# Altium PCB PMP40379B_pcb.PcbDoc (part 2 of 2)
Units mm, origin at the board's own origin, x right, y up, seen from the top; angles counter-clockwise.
Board outline 160 x 130 mm, 2 copper layers (Top Layer, Bottom Layer), stack 1.575 mm thick; 126 components, 53 nets, 295 pads, 84 vias.
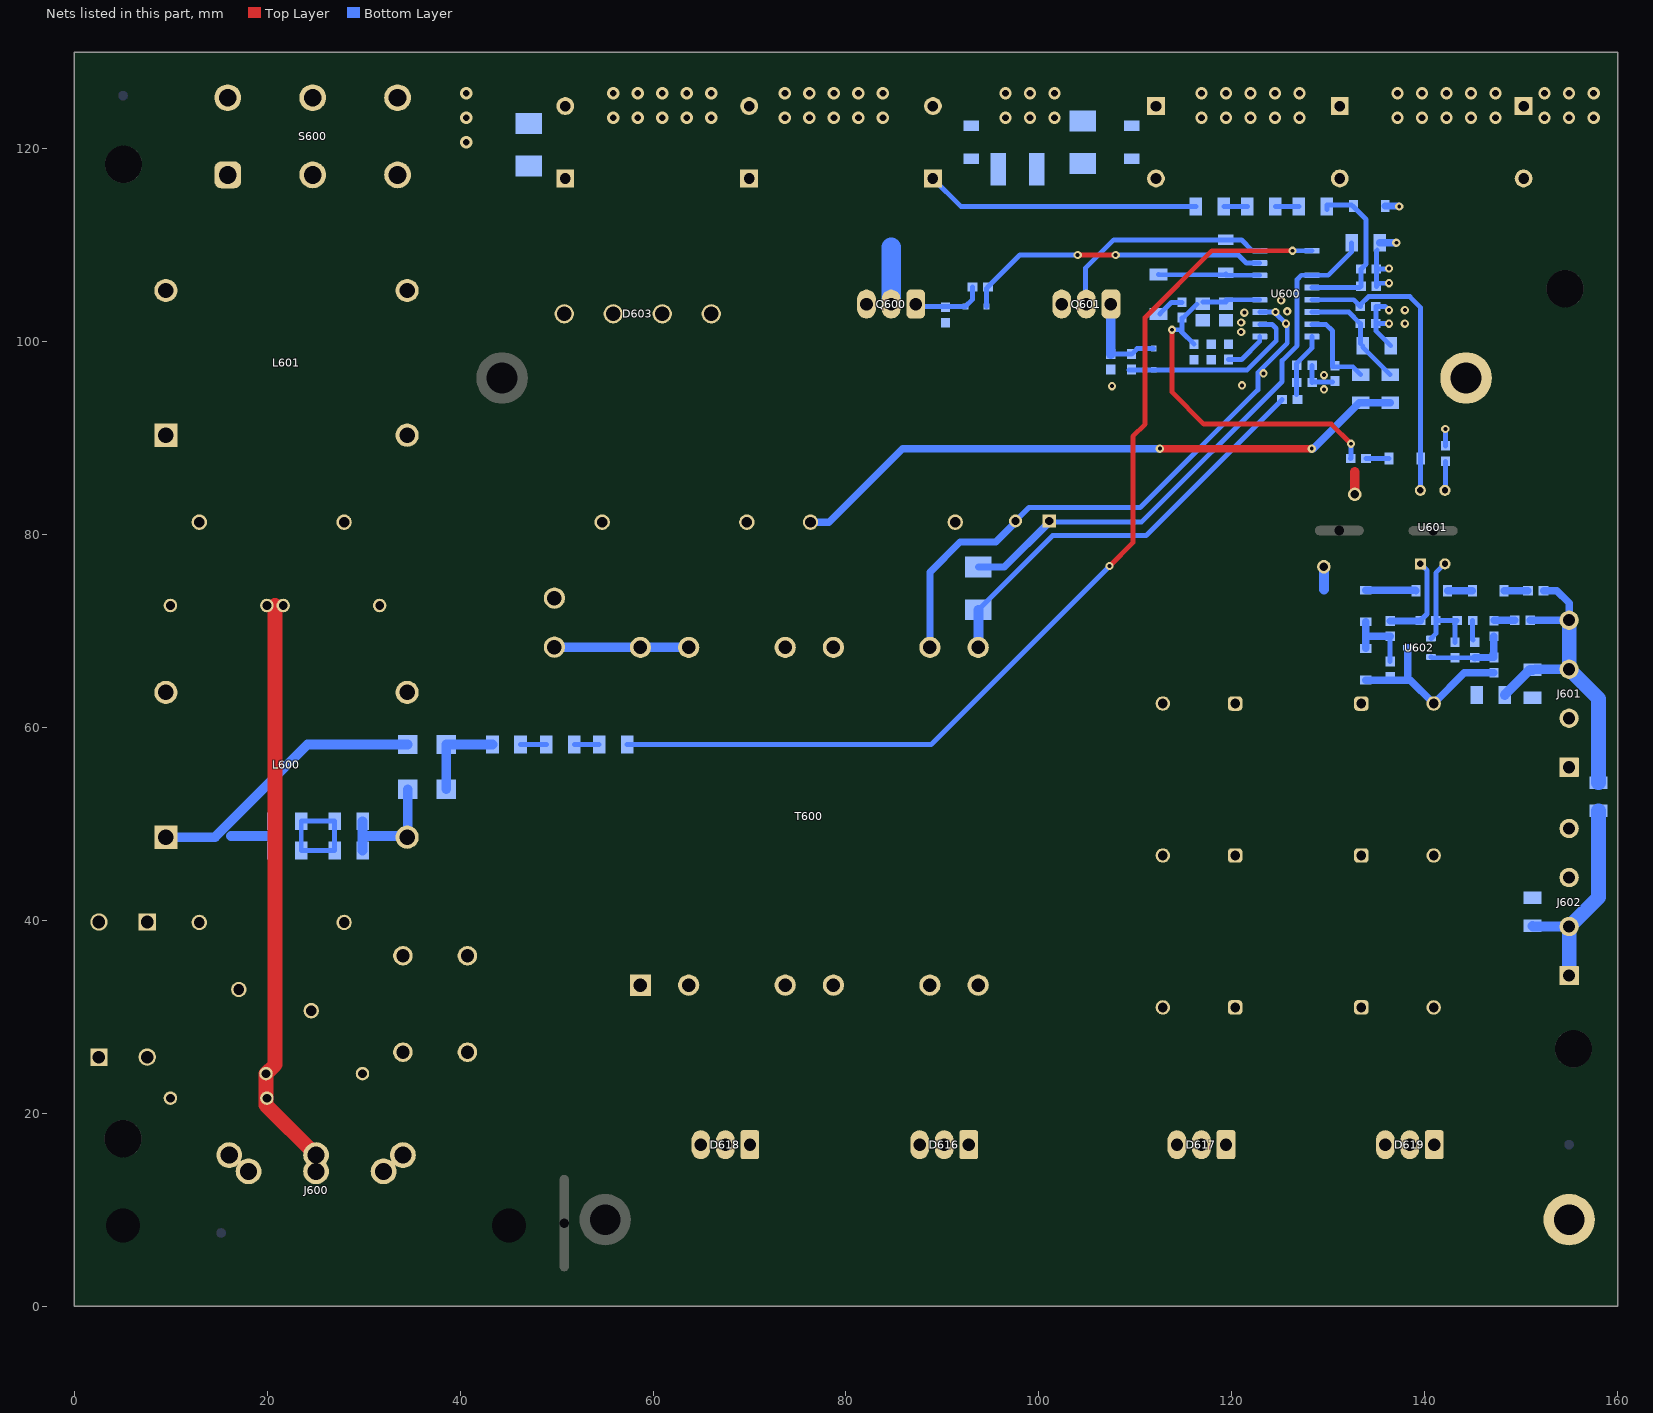
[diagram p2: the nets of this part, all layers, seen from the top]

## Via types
v1: diameter 1.27, hole 0.711, Top Layer to Bottom Layer, 55 vias
v2: diameter 0.864, hole 0.406, Top Layer to Bottom Layer, 29 vias

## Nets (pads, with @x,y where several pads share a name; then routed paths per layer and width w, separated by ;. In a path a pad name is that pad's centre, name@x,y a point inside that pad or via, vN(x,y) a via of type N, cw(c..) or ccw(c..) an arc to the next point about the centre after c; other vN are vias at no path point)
+42V: C632.1 C633.1 C634.1 C635.1 C640.1 C641.1 D616.2 D617.2 J601.3 J601.4 R624.2 R628.1 | length 34.5
  Bottom Layer w0.762: R624.2@150.914,71.12 J601.4@154.94,71.12 154.94,72.898 153.67,74.168 R628.1@152.286,74.168
  Bottom Layer w1.016: C641.1@148.262,63.373 150.855,65.966 C635.1@151.13,65.966 ; C635.1@151.458,66.04 J601.3@154.94,66.04
  Bottom Layer w1.524: J601.4@154.94,71.12 J601.3@154.94,66.04 157.988,62.992 C640.1@157.988,54.282
-42V: C631.2 C636.2 C637.2 C638.2 C639.2 C640.2 C641.2 D618.1 D618.3 D619.1 D619.3 D620.2 J602.1 J602.2 R626.1 U602.3 | length 41.2
  Bottom Layer w0.762: D620.2@133.858,64.911 138.222,64.911 ; U602.3@138.222,68.26 138.222,64.911 ; R626.1@147.146,65.659 144.085,65.659 C636.2@140.91,62.484 138.484,64.911 138.222,64.911
  Bottom Layer w1.016: C639.2@151.13,39.444 151.204,39.37 J602.2@154.94,39.37
  Bottom Layer w1.524: J602.1@154.94,34.29 J602.2@154.94,39.37 157.988,42.418 C640.2@157.988,51.382
EARTH: C602.2 C603.2 C644.2 C645.1 J600.3 pad.1@25.08,14 | length 62.9
  Top Layer w1.524: 20.828,72.644 20.828,25.066 C645.1@19.892,24.13 19.892,20.876 J600.3@25.08,15.688 pad.1@25.08,14
  Bottom Layer w1.524: pad.1@25.08,14 J600.3@25.08,15.688
HO: D606.1 R605.1 U600.15 | length 32
  Top Layer w0.508: v2(104.013,108.966) v2(107.95,108.966)
  Bottom Layer w0.508: D606.1@94.572,103.632 94.572,105.519 R605.1@94.717,105.664 98.019,108.966 v2(104.013,108.966) ; v2(107.95,108.966) 120.65,108.966 121.48,108.136 U600.15@122.882,108.136
HS: C628.2 J603.1 Q600.3 Q601.2 R606.1 U600.16 | length 23.7
  Bottom Layer w0.508: Q601.2@104.838,103.632 104.838,107.632 107.745,110.539 120.982,110.539 122.115,109.406 U600.16@122.882,109.406
LO: D607.1 R607.1 U600.10 | length 19.6
  Bottom Layer w0.508: R607.1@109.347,97.071 D607.1@111.887,97.071 121.582,97.071 124.587,100.076 124.587,101.346 124.147,101.786 U600.10@122.882,101.786
NetC600_1: C600.1 D600.2 L600.1 R600.1 R629.2 R631.2 XF2.1 XF2.2 | length 36.5
  Bottom Layer w1.016: L600.1@9.515,48.634 14.598,48.634 24.206,58.242 D600.2@34.576,58.242 ; 16.256,48.768 20.648,48.768 ; R631.2@20.648,47.244 20.648,48.768 ; R629.2@20.648,50.292 20.648,48.768
NetC600_2: C600.2 D601.2 L600.2 R600.2 R604.1 R630.1 R632.1 R633.1 | length 12.7
  Bottom Layer w1.016: R632.1@29.898,47.244 29.898,48.768 ; R630.1@29.898,50.292 29.898,48.768 ; D601.2@34.576,53.594 34.576,48.695 34.503,48.768 29.898,48.768
NetC601_1: C601.1 C602.1 L600.4 L601.1
NetC601_2: C601.2 C603.1 L600.3 L601.2
NetC605_2: C605.2 C606.2 C607.2 C608.1 C609.1 C610.1 C611.2 C612.1 D604.2 D605.1 S600.3 S600.6
  other v1: 40.64,120.65 40.64,123.19 55.88,123.19 58.42,123.19 60.96,123.19 63.5,123.19 66.04,123.19 73.66,123.19 76.2,123.19 78.74,123.19 81.28,123.19 83.82,123.19 96.52,123.19 99.06,123.19 101.6,123.19 116.84,123.19 119.38,123.19 121.92,123.19 124.46,123.19 127,123.19 137.16,123.19 139.7,123.19 142.24,123.19 144.78,123.19 147.32,123.19 152.4,123.19 154.94,123.19 157.48,123.19 40.64,125.73 55.88,125.73 58.42,125.73 60.96,125.73 63.5,125.73 66.04,125.73 73.66,125.73 76.2,125.73 78.74,125.73 81.28,125.73 83.82,125.73 96.52,125.73 99.06,125.73 101.6,125.73 116.84,125.73 119.38,125.73 121.92,125.73 124.46,125.73 127,125.73 137.16,125.73 139.7,125.73 142.24,125.73 144.78,125.73 147.32,125.73 152.4,125.73 154.94,125.73 157.48,125.73
NetC613_2: C613.2 C614.1 C615.1 C616.1 T600.12 T600.13 | length 65.2
  Top Layer w0.762: v2(112.522,88.9) v2(128.27,88.9)
  Bottom Layer w0.762: C614.1@76.32,81.28 78.232,81.28 85.852,88.9 v2(112.522,88.9) ; v2(128.27,88.9) 128.414,88.9 133.187,93.673 C616.1@133.35,93.673 C615.1@136.398,93.673
NetC615_2: C615.2 C624.2 R611.2 U600.6 | length 11.7
  Bottom Layer w0.508: U600.6@128.282,103.056 132.11,103.056 C624.2@133.312,101.854 R611.2@133.312,99.807 ; R611.2@133.551,99.568 133.551,99.42 C615.2@136.398,96.573
NetC616_2: C616.2 C617.1 U600.7 | length 9.4
  Bottom Layer w0.508: U600.7@128.282,101.786 129.735,101.786 130.429,101.092 130.429,97.391 132.532,97.391 C616.2@133.35,96.573
NetC623_1: C623.1 R613.1 R614.2 U600.9 | length 4.5
  Bottom Layer w0.508: C623.1@119.634,98.131 120.991,98.131 122.882,100.022 U600.9@122.882,100.516
NetC626_1: C626.1 D612.2 U600.5 U601.4 | length 31.5
  Bottom Layer w0.508: U600.5@128.282,104.326 132.618,104.326 C626.1@133.312,103.632 ; C626.1@133.312,103.649 133.312,103.811 134.149,104.648 138.43,104.648 139.526,103.552 U601.4@139.526,84.582
NetC627_1: C627.1 D621.1 R617.1 R618.2 U600.4 | length 17.1
  Bottom Layer w0.508: U600.4@128.282,105.596 R618.2@133.241,105.596 ; R617.1@129.829,113.7 R617.1@129.829,114.012 ; R617.1@129.829,114.139 132.411,114.139 132.504,114.046 133.893,112.657 133.893,108.026 C627.1@133.368,107.501 R618.2@133.368,105.723
NetC628_1: C628.1 D611.1 U600.14 | length 10.6
  Bottom Layer w0.508: D611.1@112.395,106.942 112.411,106.926 119.294,106.926 C628.1@119.38,107.012 ; C628.1@119.354,106.866 U600.14@122.882,106.866
NetC629_1: C629.1 R622.1 | length 2
  Bottom Layer w0.508: C629.1@144.941,71.073 144.941,69.128 R622.1@145.01,69.06
NetC629_2: C629.2 C630.2 R621.1 U601.2 U602.1 | length 12.9
  Bottom Layer w0.508: U602.1@140.622,69.21 141.131,69.72 R621.1@141.131,71.073 ; U601.2@142.066,76.962 141.131,76.027 R621.1@141.131,71.073 ; C630.2@143.125,68.825 143.125,70.857 C629.2@143.341,71.073 R621.1@141.131,71.073
NetC630_1: C630.1 R622.2 R625.1 R626.2 U602.2 | length 8.8
  Bottom Layer w0.508: U602.2@140.622,67.31 140.706,67.225 R622.2@145.157,67.225
  Bottom Layer w0.762: R622.2@145.157,67.225 145.191,67.259 R626.2@147.146,67.259 R625.1@147.146,69.469
NetC631_1: C631.1 D613.2 D620.1 R627.2 | length 8
  Bottom Layer w0.508: C631.1@136.398,66.84 R627.2@136.398,69.442
  Bottom Layer w0.762: D620.1@133.858,68.185 133.858,69.342 ; D613.2@133.858,70.956 133.858,69.342 ; R627.2@136.398,69.442 133.958,69.442 133.858,69.342
NetC644_1: C644.1 J600.1 pad.3 XF1.1 XF1.2
NetC645_2: C645.2 J600.2 pad.2@32.08,14 R604.2 R633.2
NetD600_1: D600.1 D601.1 R601.2 | length 9.4
  Bottom Layer w1.016: D601.1@38.576,53.594 D600.1@38.576,58.242 38.578,58.24 R601.2@43.367,58.24
NetD603_2: D603.2 L601.3 S600.1 S600.2 S600.4 S600.5
NetD603_3: D603.3 L601.4
NetD606_2: D606.2 Q600.1 R605.2 R606.2 | length 7.5
  Bottom Layer w0.508: Q600.1@87.226,103.632 D606.2@92.372,103.632 93.117,104.377 R605.2@93.117,105.664
NetD607_2: D607.2 Q601.1 R607.2 R608.2 | length 9.9
  Bottom Layer w0.508: R608.2@107.442,98.702 R607.2@109.601,98.702 110.17,99.271 D607.2@111.887,99.271
  Bottom Layer w1.016: R608.2@107.442,98.702 Q601.1@107.442,103.886
NetD608_2: D608.2 R609.2 T600.9 | length 44.4
  Bottom Layer w0.508: D608.2@93.726,72.212 101.397,79.883 111.087,79.883 R609.2@125.184,93.98
  Bottom Layer w1.016: T600.9@93.7,68.3 93.726,68.326 D608.2@93.726,72.212
NetD611_2: D611.2 R612.2 | length 2.8
  Bottom Layer w0.508: D611.2@112.522,102.862 113.711,104.051 R612.2@114.808,104.051
NetD612_1: D612.1 R620.1 | length 2.4
  Bottom Layer w0.508: R620.1@133.896,87.884 D612.1@136.285,87.884
NetD613_1: D613.1 D614.2 | length 5.2
  Bottom Layer w0.762: D613.1@133.858,74.231 139.016,74.231 D614.2@139.079,74.168
NetD614_1: D614.1 D615.2 | length 2.6
  Bottom Layer w0.762: D614.1@142.353,74.168 D615.2@144.921,74.168
NetD615_1: D615.1 R628.2 | length 2.5
  Bottom Layer w0.762: D615.1@148.195,74.168 R628.2@150.686,74.168
NetD616_1: D616.1 D616.3 D618.2 T600.1 T600.2
NetD617_1: D617.1 D617.3 D619.2 T600.7 T600.8
NetJ603_2: J603.2 T600.15 T600.16 | length 13.9
  Bottom Layer w1.016: J603.2@49.784,68.326 63.674,68.326 T600.15@63.7,68.3
NetR601_1: R601.1 R602.2 | length 2.7
  Bottom Layer w0.508: R601.1@46.267,58.24 R602.2@48.955,58.24
NetR602_1: R602.1 R603.2 | length 2.6
  Bottom Layer w0.508: R602.1@51.855,58.24 R603.2@54.416,58.24
NetR603_1: R603.1 U600.1 | length 105.1
  Top Layer w0.508: v2(107.315,76.74) 109.728,79.153 109.728,90.17 110.998,91.44 110.998,102.489 117.915,109.406 v2(126.27,109.406)
  Bottom Layer w0.508: R603.1@57.32,58.24 88.815,58.24 v2(107.315,76.74) ; v2(126.27,109.406) U600.1@128.282,109.406
NetR615_1: R615.1 R616.2 | length 2.4
  Bottom Layer w0.508: R615.1@119.161,114.012 R616.2@121.595,114.012
NetR616_1: R616.1 R617.2 | length 2.4
  Bottom Layer w0.508: R616.1@124.495,114.012 R617.2@126.929,114.012
NetR619_2: R619.2 U601.3 | length 3
  Bottom Layer w0.508: U601.3@142.066,84.582 142.113,84.629 R619.2@142.113,87.592
NetR621_2: R621.2 R627.1 U601.1 | length 9.6
  Bottom Layer w0.508: U601.1@139.526,76.962 140.208,76.28 140.208,71.767 139.531,71.09 R621.2@139.531,71.073
  Bottom Layer w0.762: R627.1@136.398,71.042 139.5,71.042 R621.2@139.531,71.073
NetR624_1: R624.1 R625.2 | length 2.2
  Bottom Layer w0.508: R625.2@147.146,71.069 R625.2@147.197,71.069
  Bottom Layer w0.762: R625.2@147.197,71.12 R624.1@149.314,71.12
NetR629_1: R629.1 R630.2 R631.1 R632.2 | length 13
  Bottom Layer w0.508: R631.1@23.548,47.244 R632.2@26.998,47.244 R630.2@26.998,50.292 R629.1@23.548,50.292 R631.1@23.548,47.244
OV: C625.1 R609.1 R610.2 U600.8 | length 6.7
  Bottom Layer w0.508: 126.696,96.278 126.708,96.266 ; 126.708,94.488 126.708,96.266 ; U600.8@128.282,100.516 128.282,99.326 128.016,99.06 126.708,97.752 C625.1@126.708,97.536 126.708,96.266
PGND: C608.2 C609.2 C610.2 C612.2 C614.2 C617.2 C618.2 C620.1 C621.2 C622.2 C623.2 C624.1 C625.2 C626.2 C627.2 C642.2 C646.2 D603.4 D605.2 D621.2 H600.2 Q601.3 R608.1 R610.1 R611.1 R614.1 R618.1 R619.1 T600.10 U600.11 | length 86.4
  Top Layer w1.016: 132.715,86.487 132.726,86.476 C642.2@132.726,84.162
  Bottom Layer w0.508: C618.2@97.564,81.407 98.961,82.804 110.49,82.804 122.682,94.996 122.682,96.266 122.682,96.774 125.73,99.822 125.73,101.727 124.401,103.056 U600.11@122.882,103.056 ; C625.2@128.308,97.536 R610.1@128.308,95.758 128.341,95.791 C617.2@130.429,95.791 ; C620.1@135.054,109.474 134.968,109.388 C627.2@134.968,107.501 ; v2(136.271,101.854) C624.1@134.912,101.854 ; v2(136.271,103.251) 135.89,103.632 C626.2@134.912,103.632 C624.1@134.912,101.854 ; v2(136.271,106.045) 135.29,106.045 R618.1@134.968,105.723 C627.2@134.968,107.501 ; v2(136.271,107.569) 136.203,107.501 C627.2@134.968,107.501 ; R611.1@136.451,99.568 134.912,101.107 C624.1@134.912,101.854 ; R619.1@142.113,89.192 v2(142.113,90.932)
  Bottom Layer w0.762: T600.10@88.7,68.3 88.7,76.099 91.821,79.22 95.504,79.22 97.564,81.28 C618.2@97.564,81.407 ; C620.1@135.308,110.236 v2(137.033,110.236) ; D621.2@135.876,114.046 137.287,114.046 v2(137.338,113.995)
  other v2: 129.54,95.047 107.569,95.377 121.031,95.453 129.54,96.52 123.266,96.698 120.955,100.99 125.603,101.854 137.922,101.854 120.955,101.981 121.285,102.997 124.519,103.056 125.73,103.124 137.922,103.251 125.095,104.267
RVCC: C621.1 C622.1 R612.1 R613.2 R620.2 U600.12 | length 41.2
  Top Layer w0.508: v2(113.792,101.219) 113.792,94.742 117.094,91.44 130.302,91.44 v2(132.334,89.408)
  Bottom Layer w0.508: v2(113.792,101.219) 114.577,101.219 114.808,100.988 ; R612.1@114.808,102.4 114.903,102.4 C621.1@116.37,103.867 ; R612.1@114.808,102.451 114.808,100.988 ; R613.2@116.078,99.718 114.808,100.988 ; C621.1@116.967,104.089 C622.1@119.38,104.089 ; C622.1@119.38,104.326 U600.12@122.882,104.326 ; R620.2@132.296,87.884 132.334,87.922 v2(132.334,89.408)
SGND: C632.2 C633.2 C634.2 C635.2 C636.1 C637.1 C638.1 C639.1 C642.1 H602.2 J601.1 J601.2 J602.3 J602.4 T600.4 T600.5 | length 2.4
  Bottom Layer w1.016: C642.1@129.526,76.662 129.526,74.309 129.54,74.295
VCC: C618.1 C620.2 D608.1 U600.3 | length 58.4
  Bottom Layer w0.508: C618.1@101.064,81.28 110.617,81.28 125.197,95.86 125.197,98.019 126.746,99.568 126.746,106.426 127.186,106.866 U600.3@128.282,106.866 129.98,106.866 132.408,109.294 C620.2@132.408,110.236
  Bottom Layer w0.762: D608.1@93.726,76.632 96.416,76.632 C618.1@101.064,81.28
VDC: C605.1 C606.1 C607.1 C611.1 C613.1 C646.1 D603.1 D604.1 Q600.2 R615.2 | length 34.3
  Bottom Layer w0.508: C607.1@89.01,116.9 91.898,114.012 R615.2@116.261,114.012
  Bottom Layer w2.032: Q600.2@84.676,103.886 84.676,109.786
pads on no net: FID1.1 FID2.1 FID3.1 H1.0 H1.MH H2.0 H3.0 H3.MH H4.0 H5.0 H5.MH H6.0 H7.0 H7.MH H8.0 H600.1 H602.1 J600.MH1 J600.MH2

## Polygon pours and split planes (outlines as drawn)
NetC613_2 on Bottom Layer "Bottom Layer-No Net 20" (solid, remove dead copper, pour order 102): 68.58,64.008 69.088,63.5 80.264,63.5 80.772,64.008 80.772,83.566 80.518,83.82 70.104,83.82 68.58,82.296
HS on Bottom Layer "Top Layer-No Net 9" (solid, remove dead copper, pour order 100): 82.779,105.664 83.109,105.334 83.109,103.31 84.676,101.743 88.522,101.743 89.187,102.408 95.423,102.408 95.834,102.819 95.834,105.486 98.501,108.153 104.706,108.153 105.029,108.153 105.537,108.661 105.842,108.356 105.842,107.696 105.842,91.872 104.902,90.932 84.355,90.932 79.275,85.852 69.596,85.852 66.548,82.804 66.548,70.612 66.294,70.358 41.656,70.358 41.402,70.612 41.402,76.962 41.91,77.47 56.388,77.47 57.658,78.74 57.658,87.122 71.577,101.041 75.895,101.041 80.518,105.664
VDC on Bottom Layer "Bottom Layer-No Net 18" (solid, remove dead copper, pour order 96): 55.499,79.121 42.037,79.121 41.402,79.756 41.402,115.062 45.72,119.38 96.774,119.38 96.774,109.601 93.98,106.807 79.415,106.807 75.167,102.616 70.934,102.616 56.134,87.816 56.134,79.756
NetC605_2 on Bottom Layer "Bottom Layer-No Net 17" (solid, remove dead copper, pour order 94): 30.274,129.54 159.512,129.54 160.02,129.032 160.02,121.539 44.577,121.539 38.481,115.443 32.385,115.443 30.274,117.554
NetD603_2 on Bottom Layer "Bottom Layer-No Net 16" (solid, remove dead copper, pour order 92): 11.557,111.887 21.844,101.6 38.1,101.6 38.354,101.854 38.354,105.918 27.686,116.586 27.686,129.794 11.557,129.794
NetC601_2 on Bottom Layer "Bottom Layer-No Net 4" (solid, remove dead copper, pour order 14): 38.494,91.567 38.113,91.948 27.432,91.948 26.67,91.186 26.67,62.484 27.356,61.798 37.973,61.798 38.481,62.306
NetC601_1 on Bottom Layer "Bottom Layer-No Net 3" (solid, remove dead copper, pour order 12): 1.016,91.313 1.778,92.075 13.589,92.075 14.224,91.44 14.224,62.89 13.132,61.798 1.702,61.798 1.016,62.484 1.016,62.992 1.016,88.138 1.016,89.535
SGND on Bottom Layer "BOTTOM_LAYER_SGND_P112" (solid, remove dead copper, pour order 112): 108.204,65.1 119.685,76.581 119.888,76.581 132.588,76.581 132.588,63.843 132.613,63.818 137.922,63.818 139.927,61.813 149.547,61.813 149.547,63.028 151.035,64.516 159.975,64.516 159.975,0.002 52.197,0.002 52.197,36.271 60.833,44.907 100.686,44.882 100.686,44.894 108.204,52.413
NetD617_1 on Bottom Layer "Bottom Layer-No Net 23" (solid, remove dead copper, pour order 108): 100.584,13.462 138.655,13.462 139.446,14.172 139.446,24.13 135.382,28.194 108.204,28.194 101.6,34.798 87.122,34.798 86.36,34.036 86.36,27.686
PGND on Bottom Layer "Bottom Layer-No Net 19" (solid, remove dead copper, pour order 122): 131.189,94.49 131.189,105.717 130.708,106.197 107.417,106.197 106.934,105.698 106.934,90.942 113.401,90.942 114.564,89.779 114.564,88.071 111.379,84.887 100.266,84.9 94.869,79.502 94.869,79.096 95.123,78.842 95.91,78.842 99.786,82.717 114.315,82.717 116.827,85.204 116.84,85.217 124.493,92.87 129.569,92.87
PGND on Bottom Layer "Bottom Layer-No Net 25" (solid, pour order 124): 99.69,119.502 99.182,119.502 99.06,119.38 99.06,116.459 99.238,116.281 113.106,116.281 113.792,116.967 129.719,116.967 134.671,112.015 134.671,99.517 136.271,97.917 139.192,97.917 140.462,96.647 140.462,89.281 140.97,88.773 143.256,88.773 143.383,88.646 143.383,85.217 159.893,85.217 159.893,119.507 99.695,119.507
-42V on Bottom Layer "Bottom Layer-No Net 26" (solid, remove dead copper, pour order 126): 133.096,64.262 138.176,64.262 140.208,62.23 144.526,62.23 147.231,64.935 147.839,64.935 147.839,66.029 147.701,66.167 140.987,66.167 139.446,67.708 139.446,70.561 133.096,70.561
NetC644_1 on Bottom Layer "Top Layer-No Net" (solid, remove dead copper, pour order 134): 9.076,26.924 20,16 20,13 19,12 0,12 0,14 0,26.924
NetC645_2 on Bottom Layer "Bottom Layer-No Net" (solid, remove dead copper, pour order 132): 28.956,14.044 31,12 43,12 44.069,13.069 44.069,26.797 43.434,27.432 32.004,27.432 28.956,24.384
NetC600_1 on Bottom Layer "Bottom Layer-No Net 1" (solid, remove dead copper, pour order 128): 17.399,30.353 17.399,50.927 16.891,51.435 7.874,51.435 6.731,50.292 6.731,46.863 11.938,41.656 11.938,35.306 11.43,34.798 9.398,34.798 8.89,35.306 8.89,41.656 7.683,42.862 1.206,42.862 0,41.656 0,34.29 4.318,29.972 15.748,29.972 17.018,29.972
NetC600_2 on Bottom Layer "Bottom Layer-No Net 2" (solid, remove dead copper, pour order 130): 34.099,32.067 40.957,32.067 44.069,35.179 44.069,43.434 37.465,50.038 35.306,50.038 33.528,50.038 32.805,49.315 32.805,49.276 32.793,49.264 32.793,44.985 31.242,43.434 28.194,43.434 24.638,39.878 24.638,29.464 25.146,28.956 30.988,28.956
PGND on Top Layer "Bottom Layer-No Net 19" (solid, remove dead copper, pour order 98): 64.846,85.979 65.303,85.522 80.95,85.522 87.605,78.867 92.71,78.867 98.933,85.09 160.02,85.09 160.02,119.507 72.644,119.507 64.846,111.709 64.846,100.482
NetD603_2 on Top Layer "Top Layer-No Net 8" (solid, remove dead copper, pour order 90): 30.963,99.771 57.226,99.771 57.658,100.203 57.658,105.41 56.439,106.629 30.912,106.629 30.48,106.197 30.48,100.254
NetD603_3 on Top Layer "Top Layer-No Net 7" (solid, remove dead copper, pour order 88): 63.551,100.178 63.144,99.771 59.36,99.771 58.928,100.203 58.928,101.879 58.928,105.918 57.226,107.62 29.642,107.62 22.86,100.838 0,100.838 0,113.919 61.087,113.919 63.551,111.455
NetD617_1 on Top Layer "Bottom Layer-No Net 11" (solid, remove dead copper, pour order 54): 112.008,53.85 109.728,53.85 109.728,63.964 110.236,63.964 127,63.964 127,48.528 124.029,45.557 123.923,45.451 123.19,44.718 123.19,43.136 123.952,42.374 125.984,42.374 125.984,40.342 119.38,40.342 118.318,41.404 118.318,47.54
NetC601_1 on Top Layer "Bottom Layer-No Net 3" (solid, remove dead copper, pour order 64): 13.589,92.075 14.224,91.44 14.224,62.89 13.132,61.798 1.702,61.798 1.016,62.484 1.016,62.547 1.016,62.992 1.016,88.138 1.016,91.313 1.778,92.075
NetC601_2 on Top Layer "Bottom Layer-No Net 4" (solid, remove dead copper, pour order 66): 27.356,61.798 26.67,62.484 26.67,91.186 27.432,91.948 27.686,91.948 38.1,91.948 38.481,91.567 38.481,62.306 37.973,61.798
NetC644_1 on Top Layer "Top Layer-No Net" (solid, remove dead copper, pour order 68): 9.076,26.924 20,16 20,13 19,12 0,12 0,13 0,14 0,26.924
NetC645_2 on Top Layer "Bottom Layer-No Net" (solid, remove dead copper, pour order 70): 32.004,27.432 28.956,24.384 28.956,14.044 31,12 43,12 44.069,13.069 44.069,26.797 43.434,27.432
NetC600_2 on Top Layer "Bottom Layer-No Net 2" (solid, remove dead copper, pour order 74): 24.638,29.464 25.146,28.956 30.988,28.956 34.099,32.067 40.957,32.067 44.069,35.179 44.069,43.434 37.465,50.038 35.306,50.038 33.528,50.038 32.766,49.276 32.766,44.958 31.242,43.434 28.194,43.434 24.638,39.878
NetC600_1 on Top Layer "Bottom Layer-No Net 1" (solid, remove dead copper, pour order 72): 17.399,30.353 17.399,50.673 16.637,51.435 7.874,51.435 6.731,50.292 6.731,46.863 11.938,41.656 11.938,35.306 11.43,34.798 9.398,34.798 8.89,35.306 8.89,41.656 7.683,42.862 1.206,42.862 0,41.656 0,34.29 4.318,29.972 15.748,29.972 17.018,29.972
-42V on Top Layer "Bottom Layer-No Net 21" (solid, remove dead copper, pour order 104): 52.197,0.002 52.197,17.907 53.086,18.796 65.575,18.796 65.892,18.479 65.892,15.134 66.548,14.478 68.169,14.478 69.088,15.397 69.088,18.542 69.342,18.796 72.544,18.796 78.245,13.095 80.517,10.822 94.388,10.822 96.661,13.095 122.823,13.095 129.794,20.066 137.922,28.194 137.922,62.23 139.573,63.881 143.023,63.881 160.02,63.881 160.02,0.047 159.975,0.002
+42V on Top Layer "Bottom Layer-No Net 24" (solid, remove dead copper, pour order 114): 122.58,13.768 137.275,28.462 137.275,62.428 139.387,64.541 159.975,64.541 159.975,76.581 119.888,76.581 119.685,76.581 108.204,65.1 108.204,52.413 108.16,52.368 100.762,44.958 93.472,44.958 85.713,37.199 85.713,13.768
NetD616_1 on Top Layer "Bottom Layer-No Net 22" (solid, remove dead copper, pour order 106): 52.705,19.558 52.324,19.939 52.324,35.306 52.578,35.56 64.008,35.56 68.326,31.242 78.994,31.242 88.646,21.59 88.646,18.259 94.996,18.259 95.659,17.596 95.659,13.109 93.359,10.809 81.393,10.809 76.962,15.24 67.072,15.24 66.548,15.764 66.548,19.05 66.04,19.558
NetC605_2 on Top Layer "Bottom Layer-No Net 17" (solid, remove dead copper, pour order 120): 30.274,129.54 159.512,129.54 160.02,129.032 160.02,121.412 44.45,121.412 38.862,115.824 32.004,115.824 30.274,117.554
NetC613_2 on Top Layer "Bottom Layer-No Net 20" (solid, remove dead copper, pour order 136): 68.58,64.008 69.088,63.5 80.264,63.5 80.772,64.008 80.772,83.566 80.518,83.82 70.104,83.82 68.58,82.296

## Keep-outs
Keep-Out Layer:
  text ".Layer_Name" at 14.656,-21.806 h1.52

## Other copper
Top Layer:
  text ".Layer_Name" at 14.656,-21.806 h1.52
Bottom Layer:
  rectangle net NetJ603_2: 41.402,63.5 66.548,69.85
  text ".Layer_Name" at 14.656,-21.806 h1.52

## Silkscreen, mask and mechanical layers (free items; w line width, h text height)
Top Overlay:
  rectangle: 41.605,91.924 149.129,100.242
  rectangle: 52.197,4.777 159.721,13.095
  text "+Vout" at 148.59,65.532 h2.54 r90
  text "SGND" at 148.59,55.118 h2.54 r90
  text "SGND" at 148.844,43.942 h2.54 r90
  text "-Vout" at 148.844,33.782 h2.54 r90
  text ".Layer_Name" at 14.656,-21.806 h1.52
Bottom Overlay:
  rectangle: 120.04,6.858 127.66,9.398
  lines w0.127: 44.12,0.025 44.12,39.599 57.556,53.035 97.434,53.035 100.127,55.728 100.127,68.478 116.307,84.658 159.944,84.658 ; 52.121,0.002 52.121,36.322 60.808,45.009 100.711,45.009 108.153,52.451 108.153,65.151 119.659,76.657 159.944,76.657 ; 142.367,66.04 142.494,66.04 142.748,66.294 ; 144.272,65.405 144.399,65.405 145.288,66.294
  text "+Vout" at 158.75,71.374 h2.54 r90
  text "SGND" at 158.75,62.484 h2.54 r90
  text "SGND" at 158.75,49.53 h2.54 r90
  text "-Vout" at 158.75,39.37 h2.54 r90
  text "'.PRJ_Number'.PCB_Rev-" at 142.392,7.214 h2.75
  text ".Layer_Name" at 14.656,-21.806 h1.52
Top Paste:
  text ".Layer_Name" at 14.656,-21.806 h1.52
Bottom Paste:
  text ".Layer_Name" at 14.656,-21.806 h1.52
Top Solder:
  text ".Layer_Name" at 14.656,-21.806 h1.52
  text ".Layer_Name" at 14.656,-21.806 h1.52
Bottom Solder:
  drawing of 216 lines, arcs and shapes, not listed
  text ".Layer_Name" at 14.656,-21.806 h1.52
Drill Guide:
  text ".Layer_Name" at 14.656,-21.806 h1.52
M1 Board Outline:
  lines w0.127: 61.95,45.45 90.45,45.45 90.45,45.466 90.45,48.95 61.95,48.95 61.95,45.466
  lines w0.254: 0,0 160,0 160,130 0,130 0,0
  text ".Layer_Name" at 14.656,-21.806 h1.52
M2 Board Dimensions:
  rectangle: 3.175,-10.16 12.7,-6.985
  rectangle: 0,-6.985 3.175,-3.81
  lines w0.178: 0,-6.985 25.4,-6.985 ; 3.175,-10.16 3.175,-3.81 ; 6.35,-10.16 6.35,-3.81 ; 12.7,-10.16 12.7,-3.81 ; 19.05,-10.16 19.05,-3.81 ; 0,-10.16 0,-3.81 25.4,-3.81 25.4,-10.16 0,-10.16
  text ".Layer_Name" at 14.656,-21.806 h1.52
M3 3D STEP Top:
  text ".Layer_Name" at 14.656,-21.806 h1.52
M4 3D STEP Bottom:
  text ".Layer_Name" at 14.656,-21.806 h1.52
M5 Assembly Top:
  lines w0.254: -7.417,-23.626 160.223,-23.626 ; -7.417,-18.462 160.274,-18.462 ; -7.417,-13.297 -7.417,-28.791 94.31,-28.791 160.274,-28.791 160.274,-13.297 -7.404,-13.297 -7.404,-28.791 32.614,-28.791 ; 55.194,-28.791 55.194,-13.297 ; 87.376,-18.462 87.376,-13.297 ; 108.712,-18.462 108.712,-13.297 ; 124.511,-28.956 124.511,-23.804
  text "COMPONENTS MARKED 'DNP' SHOULD NOT BE POPULATED." at 29.299,-8.09 h1.52
  text "ASSEMBLY VARIANT:" at 29.286,-11.024 h1.52
  text ".VariantName" at 55.601,-11.024 h1.52
  text "PCB VIEWED FROM TOP SIDE" at -5.804,-16.654 h1.52
  text "BOARD #:" at 57.099,-16.654 h1.52
  text ".PRJ_Number" at 70.955,-16.654 h1.52
  text "REV:" at 92.405,-16.654 h1.52
  text ".PCB_Rev" at 99.809,-16.654 h1.52
  text "SVN REV:" at 113.69,-16.654 h1.52
  text ".VersionControl_RevNumber" at 126.543,-16.654 h1.52
  text "TID #:" at 57.099,-21.819 h1.52
  text ".TID" at 70.955,-21.819 h1.52
  text "PLOT NAME =" at -5.804,-27.034 h1.52
  text ".plot_File_Name" at 14.656,-27.034 h1.52
  text "GENERATED    :" at 57.15,-27.034 h1.52
  text ".Print_Date" at 79.235,-27.034 h1.52
  text ".Print_Time" at 97.752,-27.034 h1.52
  text "TEXAS INSTRUMENTS" at 129.87,-27.034 h1.52
M6 Assembly Bottom:
  lines w0.254: -7.429,-18.474 160.261,-18.474 ; -7.379,-23.639 160.261,-23.639 ; 28.334,-28.969 28.334,-23.817 ; 44.133,-18.474 44.133,-13.31 ; 65.468,-18.474 65.468,-13.31 ; 97.65,-28.804 97.65,-13.31 ; 120.231,-28.804 160.249,-28.804 160.249,-13.31 -7.429,-13.31 -7.429,-28.804 58.534,-28.804 160.261,-28.804 160.261,-13.31
  text "COMPONENTS MARKED 'DNP' SHOULD NOT BE POPULATED." at 154.991,-8.077 h1.52
  text ".VariantName" at 128.473,-11.024 h1.52
  text "ASSEMBLY VARIANT:" at 154.864,-11.024 h1.52
  text ".VersionControl_RevNumber" at 26.302,-16.667 h1.52
  text "SVN REV:" at 39.154,-16.667 h1.52
  text ".PCB_Rev" at 53.035,-16.667 h1.52
  text "REV:" at 60.439,-16.667 h1.52
  text ".PRJ_Number" at 81.89,-16.667 h1.52
  text "BOARD #:" at 95.745,-16.667 h1.52
  text "PCB VIEWED FROM BOTTOM SIDE" at 158.648,-16.667 h1.52
  text ".TID" at 81.89,-21.831 h1.52
  text "TID #:" at 95.745,-21.831 h1.52
  text "TEXAS INSTRUMENTS" at 22.974,-27.047 h1.52
  text ".Print_Time" at 55.093,-27.047 h1.52
  text ".Print_Date" at 73.609,-27.047 h1.52
  text "GENERATED    :" at 95.694,-27.047 h1.52
  text ".plot_File_Name" at 138.189,-27.047 h1.52
  text "PLOT NAME =" at 158.648,-27.047 h1.52
M9 Title Sheet:
  drawing of 57 lines, arcs and shapes, not listed
  text "1" at 18.792,204.127 h1.78
  text "2" at 82.182,204.127 h1.78
  text "3" at 145.411,204.127 h1.78
  text "4" at 209.08,204.127 h1.78
  text "5" at 272.555,204.127 h1.78
  text "6" at 336.182,204.127 h1.78
  text "A" at -10.579,175.095 h1.78
  text "A" at 365.341,175.095 h1.78
  text "B" at -10.579,114.643 h1.78
  text "B" at 365.341,114.643 h1.78
  text "C" at -10.579,54.318 h1.78
  text "C" at 365.341,54.318 h1.78
  text "PROJECT TITLE:" at 288.125,7.048 h1.14
  text ".PRJ_Title" at 289.395,3.662 h1.78
  text "DESIGNED FOR:" at 288.125,-0.597 h1.14
  text ".PRJ_Customer" at 289.395,-4.153 h1.78
  text "D" at -10.579,-5.88 h1.78
  text "D" at 365.341,-5.88 h1.78
  text "FILE NAME:" at 288.125,-8.217 h1.14
  text ".PCB_File_Name_No_Path" at 289.395,-11.265 h1.78
  text "Texas Instruments (TI) and/or its licensors do not warrant the accuracy or completeness of this specification" at 161.9,-15.376 h1.14
  text "ENGINEER:" at 288.125,-15.583 h1.14
  text "LAYOUT BY:" at 326.352,-15.583 h1.14
  text "or any information contained therein. TI and/or its licensors do not warrant that this design will meet" at 160.757,-18.237 h1.14
  text ".PRJ_Engineer" at 289.395,-19.52 h1.78
  text "Oliver Pan" at 327.635,-19.52 h1.78
  text "the specifications, will be suitable for your application or fit for any particular purpose, or will operate in" at 160.757,-21.099 h1.14
  text ".Layer_Name" at 14.656,-21.806 h1.52
  text "ALTIUM DESIGNER VERSION:" at 326.352,-23.457 h1.14
  text "an implementation. TI and/or its licensors do not warrant that the design is production worthy. You should" at 160.757,-23.961 h1.14
  text "completely validate and test your design implementation to confirm the system functionality for your application." at 161.9,-26.822 h1.14
  text ".print_Scale" at 289.395,-26.843 h1.78
  text ".Application_BuildNumber" at 327.635,-26.843 h1.78
  text "1" at 18.792,-32.093 h1.78
  text "2" at 82.182,-32.093 h1.78
  text "3" at 145.411,-32.093 h1.78
  text "4" at 209.08,-32.093 h1.78
  text "5" at 272.555,-32.093 h1.78
  text "6" at 336.182,-32.093 h1.78
M10 Fab Notes:
  drawing of 189 lines, arcs and shapes, not listed
  text "DESIGN INFORMATION" at 314.503,161.447 h1.52
  text "MIN. TRACK WIDTH:" at 298.131,158.091 h1.52
  text "8" at 325.976,158.091 h1.52
  text "MIL" at 329.907,158.091 h1.52
  text "MIN. CLEARANCE:" at 298.131,154.938 h1.52
  text "0.2" at 324.452,154.938 h1.52
  text "mm" at 329.907,154.938 h1.52
  text "MIN. VIA PAD SIZE:" at 298.131,151.785 h1.52
  text "24" at 325.214,151.785 h1.52
  text "MIL" at 329.907,151.785 h1.52
  text "0.05mm (2MIL)" at 315.784,148.486 h1.52
  text "MINIMUM ANNULAR RING" at 289.769,148.277 h1.52
  text "EXTERNAL" at 333.768,148.277 h1.52
  text "PER" at 294.849,145.48 h1.52
  text "IPC-D-275 CLASS 2 LEVEL C" at 300.437,145.48 h1.52
  text "MIL, HOLES" at 338.238,142.928 h1.52
  text "+/-" at 328.27,142.709 h1.52
  text "+/-" at 349.961,142.709 h1.52
  text "REGISTRATION TOLERANCES:" at 289.769,142.682 h1.52
  text "METAL" at 320.243,142.682 h1.52
  text "5" at 334.879,142.683 h1.52
  text "3" at 356.037,142.683 h1.52
  text "MIL" at 358.99,142.682 h1.52
  text "HOLE SIZE TOLERANCE (UNLESS OTHERWISE SPECIFIED):" at 289.769,140.185 h1.52
  text "+/-" at 349.961,140.112 h1.52
  text "3" at 356.037,140.085 h1.52
  text "MIL" at 358.99,140.085 h1.52
  text "MATERIAL:" at 287.87,136.589 h1.52
  text "FR-4 High Tg" at 312.926,133.324 h1.52
  text "X" at 309.257,133.122 h1.52
  text "FR-408" at 298.563,133.007 h1.52
  text "OTHER" at 336.358,133.007 h1.52
  text "62 MIL (1.6mm) +/-10%" at 306.694,129.374 h1.52
  text "X" at 303.643,129.312 h1.52
  text "THICKNESS:" at 289.769,129.165 h1.52
  text "OTHER" at 339.33,129.165 h1.52
  text "TOLERANCE:" at 289.769,125.652 h1.52
  text "X" at 311.314,125.652 h1.52
  text "ANSI IPC-6012 TYPE 3 CLASS 2" at 315.836,125.652 h1.52
  text "OTHER +/-" at 315.835,121.989 h1.52
  text "BOW & TWIST:" at 289.769,118.302 h1.52
  text "X" at 311.314,118.302 h1.52
  text "ANSI IPC-6012 TYPE 3 CLASS 2" at 315.836,118.302 h1.52
  text "OTHER +/-" at 315.835,114.576 h1.52
  text "DRILLING:" at 287.87,111.258 h1.52
  text "NC_DRILL FILES" at 332.599,108.586 h1.52
  text "REFERENCE:" at 289.769,108.486 h1.52
  text "X" at 306.463,108.484 h1.52
  text "AS SHOWN" at 310.984,108.486 h1.52
  text "X" at 329.348,108.486 h1.52
  text "OTHER" at 340.168,104.873 h1.52
  text "PTH COPPER THICKNESS:" at 289.761,104.783 h1.52
  text "X" at 318.697,104.783 h1.52
  text "20-30 um" at 321.948,104.783 h1.52
  text "BOARD FINISH:" at 287.87,101.034 h1.52
  text "SILKSCREEN:" at 291.812,98.237 h1.52
  text "X" at 316.14,98.237 h1.52
  text "TOP" at 319.112,98.237 h1.52
  text "X" at 329.094,98.237 h1.52
  text "BOTTOM" at 332.091,98.237 h1.52
  text "SILKSCREEN COLOR:" at 291.812,94.295 h1.52
  text "X" at 316.115,94.295 h1.52
  text "WHITE" at 319.112,94.295 h1.52
  text "OTHER" at 332.091,94.295 h1.52
  text "X" at 319.442,90.652 h1.52
  text "GREEN" at 322.439,90.652 h1.52
  text "OTHER" at 338.136,90.652 h1.52
  text "SOLDER RESIST COLOR:" at 291.812,90.477 h1.52
  text "X" at 319.442,86.734 h1.52
  text "MATTE" at 322.439,86.734 h1.52
  text "SEMI-GLOSS" at 338.125,86.717 h1.52
  text "IMMERSION GOLD (ENIG)" at 314.819,82.345 h1.52
  text "ENEPIG" at 348.793,82.162 h1.52
  text "SURFACE FINISH:" at 287.87,82.136 h1.52
  text "X" at 310.298,82.136 h1.52
  text "IMM. TIN/SILVER OR EQUIV" at 296.24,78.649 h1.52
  text "OTHER" at 332.599,78.549 h1.52
  text "ARRAY/PANEL:" at 287.87,74.602 h1.52
  text "CUT AND TRIM PER M1 BOARD OUTLINE" at 314.819,74.393 h1.52
  text "N.C. ROUTE" at 314.819,70.94 h1.52
  text "X" at 332.295,70.94 h1.52
  text "V. SCORE" at 336.816,70.94 h1.52
  text "CERTIFICATION:" at 287.87,67.66 h1.52
  text "MATERIALS AND WORKMANSHIP FOR ALL PCBS" at 306.285,67.66 h1.52
  text "TO MEET OR EXCEED THE REQUIREMENTS OF:" at 306.285,65.271 h1.52
  text "X" at 297.078,62.003 h1.52
  text "ANSI IPC-A-600F CLASS ->" at 300.329,62.003 h1.52
  text "X" at 342.188,62.003 h1.52
  text "2" at 344.982,62.003 h1.52
  text "1" at 336.981,61.965 h1.52
  text "3" at 353.973,61.965 h1.52
  text "X" at 317.702,58.252 h1.52
  text "RoHS" at 320.953,58.252 h1.52
  text "OTHER" at 337.321,58.252 h1.52
  text "PER ORDER" at 347.407,58.252 h1.52
  text "ALL BOARDS MUST MEET OR EXCEED UL94-V0 REQUIREMENTS." at 288.569,54.345 h1.52
  text "PCB MUST BEAR THE UL94V-0 UL REGISTERED MATERIAL ID NUMBER" at 288.569,51.397 h1.52
  text "ADDITIONAL REQUIREMENTS:" at 287.87,47.094 h1.52
  text "MICROSECTION:" at 289.769,44.373 h1.52
  text "YES" at 312.775,44.373 h1.52
  text "REQUIRED" at 334.657,40.707 h1.52
  text "BARE BOARD ELEC. TEST:" at 289.769,40.634 h1.52
  text "NONE" at 322.935,40.634 h1.52
  text "X" at 331.66,40.634 h1.52
  text "PER ORDER" at 349.693,40.634 h1.52
  text "XX MIL VIAS REQUIRE NON-CONDUCTIVE FILL AND PLANARIZE" at 294.04,35.428 h1.5
  text "XX MIL VIAS REQUIRE CONDUCTIVE FILL AND PLANARIZE" at 294.243,32.787 h1.52
  text "OUTER XX MIL VIAS REQUIRE 50 OHM SINGLE-ENDED IMPEDANCE" at 294.218,28.637 h1.47
  text "LAYER 2 & 3 (INNER LAYERS) XX MIL WIDE, XX MIL SPACE / TRACES REQUIRE 100 OHM DIFFERENTIAL IMPEDANCE" at 294.015,22.65 h1.52
  text ".Layer_Name" at 14.656,-21.806 h1.52
M11 Gerber Information:
  lines w0.254: -7.417,-23.626 160.223,-23.626 ; -7.417,-18.462 160.274,-18.462 ; -7.417,-13.297 -7.417,-28.791 94.31,-28.791 160.274,-28.791 160.274,-13.297 -7.404,-13.297 -7.404,-28.791 32.614,-28.791 ; 55.194,-28.791 55.194,-13.297 ; 87.376,-18.462 87.376,-13.297 ; 108.712,-18.462 108.712,-13.297 ; 124.511,-28.956 124.511,-23.804
  text "ALL ARTWORK VIEWED FROM TOP SIDE" at -5.804,-16.654 h1.52
  text "BOARD #:" at 57.099,-16.654 h1.52
  text ".PRJ_Number" at 70.955,-16.654 h1.52
  text "REV:" at 92.405,-16.654 h1.52
  text ".PCB_Rev" at 99.809,-16.654 h1.52
  text "SVN REV:" at 113.69,-16.654 h1.52
  text ".VersionControl_RevNumber" at 126.543,-16.654 h1.52
  text "LAYER NAME =" at -5.804,-21.806 h1.52
  text "TID #:" at 57.099,-21.819 h1.52
  text ".TID" at 70.955,-21.819 h1.52
  text "PLOT NAME =" at -5.804,-27.034 h1.52
  text ".plot_File_Name" at 14.656,-27.034 h1.52
  text "GENERATED    :" at 57.15,-27.034 h1.52
  text ".Print_Date" at 79.235,-27.034 h1.52
  text ".Print_Time" at 97.752,-27.034 h1.52
  text "TEXAS INSTRUMENTS" at 129.87,-27.034 h1.52
M12 Stackup:
  drawing of 191 lines, arcs and shapes, not listed
  text "Layer" at 248.865,198.882 h1.52
  text "Name" at 259.277,198.882 h1.52
  text "Material" at 282.892,198.882 h1.52
  text "Thickness" at 304.731,198.882 h1.52
  text "Constant" at 321.236,198.882 h1.52
  text "Board Layer Stack" at 335.711,198.882 h1.52
  text "1" at 248.865,195.834 h1.52
  text "Top Overlay" at 259.277,195.834 h1.52
  text "2" at 248.865,192.786 h1.52
  text "Top Solder" at 259.277,192.786 h1.52
  text "Solder Resist" at 282.892,192.786 h1.52
  text "0.40mil" at 304.731,192.786 h1.52
  text "3.5" at 321.236,192.786 h1.52
  text "3" at 248.865,189.738 h1.52
  text "Top Layer" at 259.277,189.738 h1.52
  text "Copper" at 282.892,189.738 h1.52
  text "1.40mil" at 304.731,189.738 h1.52
  text "4" at 248.865,186.69 h1.52
  text "Dielectric1" at 259.277,186.69 h1.52
  text "FR-4" at 282.892,186.69 h1.52
  text "59.20mil" at 304.731,186.69 h1.52
  text "4.8" at 321.236,186.69 h1.52
  text "5" at 248.865,183.642 h1.52
  text "Bottom Layer" at 259.277,183.642 h1.52
  text "Copper" at 282.892,183.642 h1.52
  text "1.40mil" at 304.731,183.642 h1.52
  text "6" at 248.865,180.594 h1.52
  text "Bottom Solder" at 259.277,180.594 h1.52
  text "Solder Resist" at 282.892,180.594 h1.52
  text "0.40mil" at 304.731,180.594 h1.52
  text "3.5" at 321.236,180.594 h1.52
  text "7" at 248.865,177.546 h1.52
  text "Bottom Overlay" at 259.277,177.546 h1.52
  text ".Layer_Name" at 14.656,-21.806 h1.52
M13 Component Bodies Top:
  text ".Layer_Name" at 14.656,-21.806 h1.52
M14 Component Bodies Bottom:
  text ".Layer_Name" at 14.656,-21.806 h1.52
M15 Courtyards Top:
  text ".Layer_Name" at 14.656,-21.806 h1.52
M16 Courtyards Bottom:
  text ".Layer_Name" at 14.656,-21.806 h1.52
Drill Drawing:
  drawing of 165 lines, arcs and shapes, not listed
  text "Symbol" at 165.936,127.451 h1.83
  text "Count" at 173.57,127.451 h1.83
  text "Hole Size" at 181.249,127.451 h1.83
  text "Plated" at 196.233,127.451 h1.83
  text "Hole Type" at 202.815,127.451 h1.83
  text "Drill Layer Pair" at 212.344,127.451 h1.83
  text "Hole Tolerance" at 230.742,127.451 h1.83
  text "1" at 173.57,124.293 h1.52
  text "39.37mil (1.000mm)" at 181.249,124.293 h1.52
  text "NPTH" at 196.233,124.293 h1.52
  text "Slot" at 202.815,124.293 h1.52
  text "Top Layer - Bottom Layer" at 212.344,124.293 h1.52
  text "2" at 173.57,121.136 h1.52
  text "33.47mil (0.850mm)" at 181.249,121.136 h1.52
  text "PTH" at 196.233,121.136 h1.52
  text "Round" at 202.815,121.136 h1.52
  text "Top Layer - Bottom Layer" at 212.344,121.136 h1.52
  text "2" at 173.57,117.978 h1.52
  text "39.37mil (1.000mm)" at 181.249,117.978 h1.52
  text "NPTH" at 196.233,117.978 h1.52
  text "Slot" at 202.815,117.978 h1.52
  text "Top Layer - Bottom Layer" at 212.344,117.978 h1.52
  text "A" at 165.294,117.724 h1.4
  text "2" at 173.57,114.82 h1.52
  text "137.80mil (3.500mm)" at 181.249,114.82 h1.52
  text "NPTH" at 196.233,114.82 h1.52
  text "Round" at 202.815,114.82 h1.52
  text "Top Layer - Bottom Layer" at 212.344,114.82 h1.52
  text "E" at 165.294,114.566 h1.4
  text "4" at 173.57,111.662 h1.52
  text "25.59mil (0.650mm)" at 181.249,111.662 h1.52
  text "PTH" at 196.233,111.662 h1.52
  text "Round" at 202.815,111.662 h1.52
  text "Top Layer - Bottom Layer" at 212.344,111.662 h1.52
  text "D" at 165.294,111.409 h1.4
  text "4" at 173.57,108.505 h1.52
  text "53.15mil (1.350mm)" at 181.249,108.505 h1.52
  text "PTH" at 196.233,108.505 h1.52
  text "Round" at 202.815,108.505 h1.52
  text "Top Layer - Bottom Layer" at 212.344,108.505 h1.52
  text "4" at 173.57,105.347 h1.52
  text "125.00mil (3.175mm)" at 181.249,105.347 h1.52
  text "PTH" at 196.233,105.347 h1.52
  text "Round" at 202.815,105.347 h1.52
  text "Top Layer - Bottom Layer" at 212.344,105.347 h1.52
  text "G" at 165.294,105.093 h1.4
  text "4" at 173.57,102.189 h1.52
  text "152.00mil (3.861mm)" at 181.249,102.189 h1.52
  text "NPTH" at 196.233,102.189 h1.52
  text "Round" at 202.815,102.189 h1.52
  text "Top Layer - Bottom Layer" at 212.344,102.189 h1.52
  text "6" at 173.57,99.032 h1.52
  text "59.06mil (1.500mm)" at 181.249,99.032 h1.52
  text "PTH" at 196.233,99.032 h1.52
  text "Round" at 202.815,99.032 h1.52
  text "Top Layer - Bottom Layer" at 212.344,99.032 h1.52
  text "6" at 173.57,95.874 h1.52
  text "70.00mil (1.778mm)" at 181.249,95.874 h1.52
  text "PTH" at 196.233,95.874 h1.52
  text "Round" at 202.815,95.874 h1.52
  text "Top Layer - Bottom Layer" at 212.344,95.874 h1.52
  text "F" at 165.294,95.62 h1.4
  text "6" at 173.57,92.716 h1.52
  text "72.84mil (1.850mm)" at 181.249,92.716 h1.52
  text "PTH" at 196.233,92.716 h1.52
  text "Round" at 202.815,92.716 h1.52
  text "Top Layer - Bottom Layer" at 212.344,92.716 h1.52
  text "8" at 173.57,89.558 h1.52
  text "49.21mil (1.250mm)" at 181.249,89.558 h1.52
  text "PTH" at 196.233,89.558 h1.52
  text "Round" at 202.815,89.558 h1.52
  text "Top Layer - Bottom Layer" at 212.344,89.558 h1.52
  text "8" at 173.57,86.401 h1.52
  text "62.99mil (1.600mm)" at 181.249,86.401 h1.52
  text "PTH" at 196.233,86.401 h1.52
  text "Round" at 202.815,86.401 h1.52
  text "Top Layer - Bottom Layer" at 212.344,86.401 h1.52
  text "10" at 173.57,83.243 h1.52
  text "35.43mil (0.900mm)" at 181.249,83.243 h1.52
  text "PTH" at 196.233,83.243 h1.52
  text "Round" at 202.815,83.243 h1.52
  text "Top Layer - Bottom Layer" at 212.344,83.243 h1.52
  text "B" at 165.294,82.989 h1.4
  text "10" at 173.57,80.085 h1.52
  text "51.18mil (1.300mm)" at 181.249,80.085 h1.52
  text "PTH" at 196.233,80.085 h1.52
  text "Round" at 202.815,80.085 h1.52
  text "Top Layer - Bottom Layer" at 212.344,80.085 h1.52
  text "12" at 173.57,76.927 h1.52
  text "39.37mil (1.000mm)" at 181.249,76.927 h1.52
  text "PTH" at 196.233,76.927 h1.52
  text "Round" at 202.815,76.927 h1.52
  text "Top Layer - Bottom Layer" at 212.344,76.927 h1.52
  text "12" at 173.57,73.77 h1.52
  text "50.00mil (1.270mm)" at 181.249,73.77 h1.52
  text "PTH" at 196.233,73.77 h1.52
  text "Round" at 202.815,73.77 h1.52
  text "Top Layer - Bottom Layer" at 212.344,73.77 h1.52
  text "12" at 173.57,70.612 h1.52
  text "55.12mil (1.400mm)" at 181.249,70.612 h1.52
  text "PTH" at 196.233,70.612 h1.52
  text "Round" at 202.815,70.612 h1.52
  text "Top Layer - Bottom Layer" at 212.344,70.612 h1.52
  text "22" at 173.57,67.454 h1.52
  text "43.31mil (1.100mm)" at 181.249,67.454 h1.52
  text "PTH" at 196.233,67.454 h1.52
  text "Round" at 202.815,67.454 h1.52
  text "Top Layer - Bottom Layer" at 212.344,67.454 h1.52
  text "C" at 165.294,67.201 h1.4
  text "29" at 173.57,64.297 h1.52
  text "16.00mil (0.406mm)" at 181.249,64.297 h1.52
  text "PTH" at 196.233,64.297 h1.52
  text "Round" at 202.815,64.297 h1.52
  text "Top Layer - Bottom Layer" at 212.344,64.297 h1.52
  text "55" at 173.57,61.139 h1.52
  text "28.00mil (0.711mm)" at 181.249,61.139 h1.52
  text "PTH" at 196.233,61.139 h1.52
  text "Round" at 202.815,61.139 h1.52
  text "Top Layer - Bottom Layer" at 212.344,61.139 h1.52
  text "219 Total" at 173.57,57.981 h1.52
  text "Slot definitions :" at 165.936,55.771 h1.52
  text "Routed Path Length" at 177.384,55.771 h1.52
  text "= Calculated from tool start centre position to tool end centre position." at 191.094,55.771 h1.52
  text "Hole Length" at 177.384,54.508 h1.52
  text "= Routed Path Length + Tool Size = Slot length as defined in the PCB layout" at 186.019,54.508 h1.52
  text ".Layer_Name" at 14.656,-21.806 h1.52
M17 Embedded Cavity:
  text ".Layer_Name" at 14.656,-21.806 h1.52
M18 Embedded Assembly:
  text ".Layer_Name" at 14.656,-21.806 h1.52
M19 Embedded Keepout:
  text ".Layer_Name" at 14.656,-21.806 h1.52

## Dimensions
0,0 to 0,130 on M2 Board Dimensions
0,0 to 160,0 on M2 Board Dimensions
0,-10.16 to 25.4,-10.16 on M2 Board Dimensions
